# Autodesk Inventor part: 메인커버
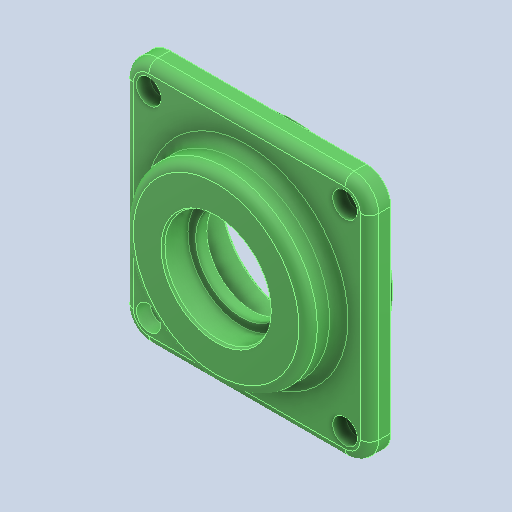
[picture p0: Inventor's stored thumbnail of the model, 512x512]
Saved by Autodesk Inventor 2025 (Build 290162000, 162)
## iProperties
Created: 2024-08
Part Number: 메인커버
Material: 알루미늄 6061
Document SubType Name: Modeling
Designer: rese9
Density: 2.71 g/cm^3
Appearance: 기본값
Author: jhkim
Sending System: Autodesk Inventor 2025
Preprocessor: ST-DEVELOPER v20
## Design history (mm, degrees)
feature "솔리드1"
node "솔리드2"
